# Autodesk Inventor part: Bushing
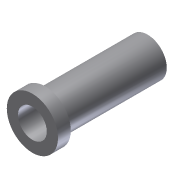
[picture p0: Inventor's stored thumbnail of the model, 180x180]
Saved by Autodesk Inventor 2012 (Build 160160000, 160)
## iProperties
Shininess: 77.0
Length Units: 11269
Angle Units: 11279
Time Units: 11290
Mass Units: 11283
Length Display Precision: 3
Angle Display Precision: 2
Created: 2002-02
Part Number: Bushing
Document SubType Name: Modeling
Designer: ***
Density: 1 g/cm^3
Material: Default
Density: 0.0
Volumn: 0.0
Area: 0.0
PropertySet Name: Model Information
Control State: 0
Master: False
Checked Out: False
Author: ***
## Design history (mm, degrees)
sketch "Sketch1"
  geometry: L1 (6.25, 50.44)-(6.25, 5.44); L2 (6.25, 5.44)-(10.625, 5.44); L3 (10.625, 5.44)-(10.625, 10.44); L4 (10.625, 10.44)-(8.125, 10.44); L5 (8.125, 10.44)-(8.125, 50.44); L6 (8.125, 50.44)-(6.25, 50.44); L7 (0.625, 34.884)-(0.625, 0)
  constraints: 14 end point, 4 parallel, 2 perpendicular, 1 vertical
  dimensions: "d0" = 20 diameter of L3 L7; "d1" = 11.25 diameter of L1 L7; "d2" = 15 diameter of L5 L7; "d4" = 5 distance of L2.end L3.end; "d5" = 45 distance of L1.start L1.end
revolve "Revolution1" sketch "Sketch1" stored, may be unused: angle "d3" = 90 deg
body "Solid1"
